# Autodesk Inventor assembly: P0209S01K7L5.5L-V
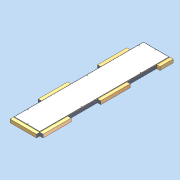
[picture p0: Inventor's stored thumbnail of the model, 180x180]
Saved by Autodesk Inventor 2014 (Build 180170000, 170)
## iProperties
Created: 2011-04
Part Number: P0209S01K7L5.5L-V
Document SubType Name: Assembly
Designer: david.appleford
Description: 0.5w x 2.25w 01 Panel - 7 Locks 5.5 Lugs LH
Mass: 32000 g
Surface Area: 43472.2 cm^2
Volume: 130143 cm^3
Density: 0.245882 g/cm^3
Cost Center: £131.00
Justset: False
Title: 0.5w x 2.25w 01 Panel - 7 Locks 5.5 Lugs LH
Author: david.appleford
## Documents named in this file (6)
- C:\Documents and Settings\john.everitt\Local Settings\My Documents\Vault\Production MkII\VIRTUAL ELEMENTS\Virtual Walls\Virtual Timber + MgO\P0209S01K7L5.5L-V.iam
- C:\Documents and Settings\john.everitt\Local Settings\My Documents\Vault\Production MkII\VIRTUAL ELEMENTS\Virtual Lugs\Superceded Lugs\LA02C3V.ipt
- C:\Documents and Settings\john.everitt\Local Settings\My Documents\Vault\Production MkII\VIRTUAL ELEMENTS\Virtual Lugs\Superceded Lugs\LA02M3V.ipt
- C:\Documents and Settings\john.everitt\Local Settings\My Documents\Vault\Production MkII\VIRTUAL ELEMENTS\Virtual Lugs\Superceded Lugs\LA02E3V.ipt
- C:\Documents and Settings\john.everitt\Local Settings\My Documents\Vault\Production MkII\Virtual Elements\Virtual Walls\Virtual Timber + MgO\P0209S01K7-V.ipt
- C:\Documents and Settings\john.everitt\Local Settings\My Documents\Vault\Production MkII\VIRTUAL ELEMENTS\Virtual Lugs\Superceded Lugs\LA01C3V.ipt
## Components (7 placed, 5 different names)
1. P0209S01K7-V:1 — Mate:1, Flush:1, Flush:2, Mate:5, Mate:6, Flush:9, Flush:10, Mate:7, Flush:11, Mate:14, Flush:12, Flush:13, Mate:15, Flush:14, Flush:15
2. LA02C3V:1 — Mate:1, Flush:1, Flush:2, Mate:9, Mate:13
3. LA02M3V:5 — Mate:6, Flush:9, Mate:12
4. LA02M3V:2 — Mate:5, Flush:10, Mate:12, Mate:13
5. LA02M3V:4 — Mate:7, Flush:11, Mate:9
6. LA02E3V:1 — Mate:14, Flush:12, Flush:13
7. LA01C3V:1 — Mate:15, Flush:14, Flush:15
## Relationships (18: Mate 9, Flush 9)
- Mate:1: P0209S01K7-V:1 ↔ LA02C3V:1
- Flush:1: P0209S01K7-V:1 ↔ LA02C3V:1
- Flush:2: P0209S01K7-V:1 ↔ LA02C3V:1
- Mate:5: P0209S01K7-V:1 ↔ LA02M3V:2
- Mate:6: P0209S01K7-V:1 ↔ LA02M3V:5
- Flush:9: P0209S01K7-V:1 ↔ LA02M3V:5
- Flush:10: P0209S01K7-V:1 ↔ LA02M3V:2
- Mate:7: P0209S01K7-V:1 ↔ LA02M3V:4
- Flush:11: P0209S01K7-V:1 ↔ LA02M3V:4
- Mate:9: LA02C3V:1 ↔ LA02M3V:4
- Mate:12: LA02M3V:5 ↔ LA02M3V:2
- Mate:13: LA02C3V:1 ↔ LA02M3V:2
- Mate:14: P0209S01K7-V:1 ↔ LA02E3V:1
- Flush:12: P0209S01K7-V:1 ↔ LA02E3V:1
- Flush:13: P0209S01K7-V:1 ↔ LA02E3V:1
- Mate:15: P0209S01K7-V:1 ↔ LA01C3V:1
- Flush:14: P0209S01K7-V:1 ↔ LA01C3V:1
- Flush:15: P0209S01K7-V:1 ↔ LA01C3V:1
## Named parameters: t = 1 mm, Cl = 2 mm
